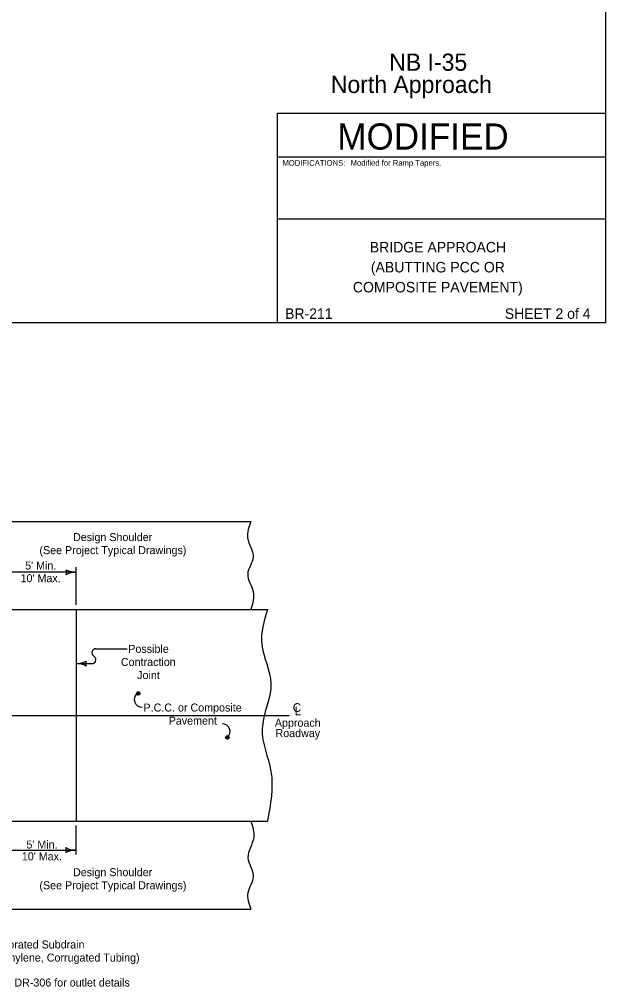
# Model space of a CAD drawing. Extents: x 10045 to 81668, y 6370 to 11018.
# Drawn here: x 15638 to 16868, y 6530 to 8561 of the extents above; entities that cross this region are included whole.
import ezdxf

# ---------------------------------------------------------------- set-up
doc = ezdxf.new("R2010")
doc.units = 0
for name, color, linetype in [('Alignment', 7, 'Continuous'), ('Bridge', 7, 'Continuous'), ('dsnStdLineWork', 7, 'Continuous'), ('Level 5', 7, 'Continuous')]:
    doc.layers.add(name, color=color, linetype=linetype)

msp = doc.modelspace()

# ---------------------------------------------------------------- linework, layer by layer
at = {"layer": 'Alignment'}
for p, q in [((15756.9, 7400.4), (15612.4, 7400.4)), ((15756.9, 7332.2), (15756.9, 7410.7)), ((15798.2, 7239.6), (15863.8, 7239.6)), ((15794, 7224.1), (15792.8, 7225.2)), ((15757.1, 7208.6), (15789.9, 7208.6)), ((15982.5, 7099.9), (15982.5, 7099.9)), ((15755.9, 6868.3), (15755.9, 6807.4)), ((15612.4, 6817), (15755.9, 6817))]:
    msp.add_line(p, q, dxfattribs=at)
for centre, radius, start, end in [((15798.2, 7231.4), 8.22, 90, 228.6908), ((15789.9, 7216.8), 8.22, 270, 48.691), ((15895.1, 7133.5), 16.4, 131.3092, 270), ((16063.2, 7066), 16.4, 311.309, 90)]:
    msp.add_arc(centre, radius, start, end, dxfattribs=at)
at = {"layer": 'Bridge'}
for p, q in [((16179.5, 8272.7), (16867.5, 8272.7)), ((16179.5, 8142.2), (16867.5, 8142.2))]:
    msp.add_line(p, q, dxfattribs=at)
msp.add_lwpolyline([(16179.5, 8364), (16867.5, 8364), (16867.5, 7924), (16179.5, 7924)], close=True, dxfattribs=at)
at = {"layer": 'dsnStdLineWork'}
for p, q in [((15612.4, 7507), (16123.2, 7507)), ((15612.4, 7322), (16158, 7322)), ((15756.9, 7322), (15756.9, 6877.9)), ((15795.3, 7223), (15794, 7224.1)), ((14687.2, 7099.9), (16203.5, 7099.9)), ((15612.4, 6877.9), (16158, 6877.9)), ((15612.4, 6692.9), (16123.2, 6692.9))]:
    msp.add_line(p, q, dxfattribs=at)
for points in [[(15886.7, 7142.6), (15887.9, 7143.1), (15889.8, 7143.7), (15890.2, 7145.6), (15889.9, 7147.3), (15888.7, 7148.8), (15886.9, 7148.7), (15885, 7148.4), (15884.1, 7146.9), (15883.9, 7145.3), (15885.1, 7143.2), (15886.4, 7143.1), (15888.3, 7143.5), (15889.9, 7144.7), (15889.8, 7146.6), (15888.6, 7148), (15886.9, 7148.2), (15885, 7147.8), (15884.8, 7146.7), (15884.4, 7145.4), (15885.3, 7143.9), (15886.6, 7143.9), (15888.2, 7144.2), (15889.4, 7145.1), (15888.8, 7146.6), (15887.6, 7147.5), (15886, 7147.6), (15885.6, 7146.7), (15885.1, 7145.8), (15885.9, 7144.5), (15887, 7144.2), (15888.1, 7144.8), (15888.2, 7146), (15887.6, 7146.8), (15886.5, 7147.1), (15886, 7146.6), (15885.7, 7146), (15886.3, 7145.1), (15887, 7144.9), (15887.8, 7145.3), (15887.6, 7146), (15887.1, 7146.4), (15886.4, 7146.3), (15886.4, 7145.8), (15887, 7145.5)], [(16073.8, 7050.3), (16075, 7050.8), (16076.9, 7051.4), (16077.2, 7053.3), (16077, 7055), (16075.8, 7056.6), (16074, 7056.4), (16072.1, 7056.2), (16071.2, 7054.7), (16071, 7053.1), (16072.1, 7051), (16073.5, 7050.8), (16075.4, 7051.3), (16076.9, 7052.5), (16076.9, 7054.3), (16075.7, 7055.7), (16074, 7055.9), (16072.1, 7055.5), (16071.8, 7054.5), (16071.4, 7053.2), (16072.3, 7051.6), (16073.7, 7051.7), (16075.3, 7051.9), (16076.4, 7052.8), (16075.8, 7054.4), (16074.6, 7055.3), (16073.1, 7055.3), (16072.7, 7054.5), (16072.2, 7053.5), (16072.9, 7052.3), (16074.1, 7052), (16075.1, 7052.5), (16075.2, 7053.7), (16074.7, 7054.5), (16073.6, 7054.8), (16073.1, 7054.4), (16072.8, 7053.7), (16073.3, 7052.8), (16074.1, 7052.6), (16074.8, 7053.1), (16074.7, 7053.7), (16074.1, 7054.1), (16073.4, 7054.1), (16073.4, 7053.5), (16074.1, 7053.3)]]:
    msp.add_lwpolyline(points, dxfattribs=at)
for centre in [(15887, 7145.9), (16074, 7053.6)]:
    msp.add_circle(centre, 3.6, dxfattribs=at)
for centre, radius, start, end in [((15719.6, 7400.4), 17.1, 342.2666, 17.7334), ((15756.9, 7444.8), 44.4, 241.9275, 270), ((15756.9, 7356), 44.4, 90, 118.0725), ((15757.1, 7253), 44.4, 270, 298.0725), ((15794.3, 7208.6), 17.1, 162.2666, 197.7334), ((15757.1, 7164.2), 44.4, 61.9275, 90), ((15718.5, 6817), 17.2, 342.2666, 17.7334), ((15755.9, 6861.6), 44.6, 241.9275, 270), ((15755.9, 6772.3), 44.6, 90, 118.0725)]:
    msp.add_arc(centre, radius, start, end, dxfattribs=at)
for points in [[(16123.2, 7507), (16116.3, 7472.7), (16128, 7432.1), (16116.6, 7396.6), (16128, 7360), (16123.2, 7322)], [(16158, 7322), (16146.1, 7249.2), (16165.4, 7166.7), (16146.9, 7071.8), (16165.4, 6982.3), (16158, 6877.9)], [(16123.2, 6877.9), (16129.2, 6843.2), (16117.2, 6801.4), (16128.2, 6761.6), (16116.9, 6727.1), (16123.2, 6692.9)]]:
    msp.add_spline(points, degree=3, dxfattribs=at)
at = {"layer": 'Level 5'}
msp.add_lwpolyline([(13732.5, 9944), (16867.5, 9944), (16867.5, 7924), (13732.5, 7924)], close=True, dxfattribs=at)

# ---------------------------------------------------------------- texts
at = {"layer": 'Alignment'}
for s, height, p in [('Design Shoulder', 16.8, (15750.2, 7465.8)), ('(See Project Typical Drawings)', 16.8, (15679.7, 7438.4)), ("5' Min.", 16.8, (15649.7, 7406.1)), ("10' Max.", 16.8, (15640.1, 7379.5)), ('Possible', 16.8, (15866.1, 7231.1)), ('Contraction', 16.8, (15850.7, 7203.6)), ('Joint', 16.8, (15884.8, 7176.1)), ('P.C.C. or Composite', 16.8, (15898, 7107.9)), ('C', 18.4, (16211.2, 7107)), ('L', 18.4, (16215.1, 7099.9)), ('Pavement', 16.8, (15950.9, 7080.4)), ('Approach', 16.8, (16173.6, 7076)), ('Roadway', 16.8, (16175, 7054.2)), ("5' Min.", 16.8, (15652.4, 6820.3)), ("10' Max.", 16.8, (15642.8, 6795.4)), ('Design Shoulder', 16.8, (15750.2, 6762.2)), ('(See Project Typical Drawings)', 16.8, (15679.7, 6734.7)), ('4" Perforated Subdrain ', 16.8, (15546.5, 6610.4)), ('(Polyethylene, Corrugated Tubing)', 16.8, (15546.5, 6582.9)), ('See DR-306 for outlet details', 16.8, (15580.9, 6530.5))]:
    msp.add_text(s, height=height, dxfattribs=at).set_placement(p)
at = {"layer": 'Bridge'}
for s, height, p in [('NB I-35', 36.09, (16413.5, 8453.3)), ('North Approach', 36.086, (16291, 8406.6)), ('MODIFIED', 55, (16304.6, 8287.8)), ('Modified for Ramp Tapers.', 12, (16332.7, 8253.8)), ('MODIFICATIONS:', 12, (16189.5, 8253.8)), ('BRIDGE APPROACH', 22, (16372.7, 8071.9)), ('(ABUTTING PCC OR', 22, (16375, 8029.9)), ('COMPOSITE PAVEMENT)', 22, (16337.3, 7987.9)), ('BR-211', 22, (16195, 7932.4)), ('SHEET 2 of 4', 22, (16656, 7932.4))]:
    msp.add_text(s, height=height, dxfattribs=at).set_placement(p)

doc.saveas('drawing.dxf')
